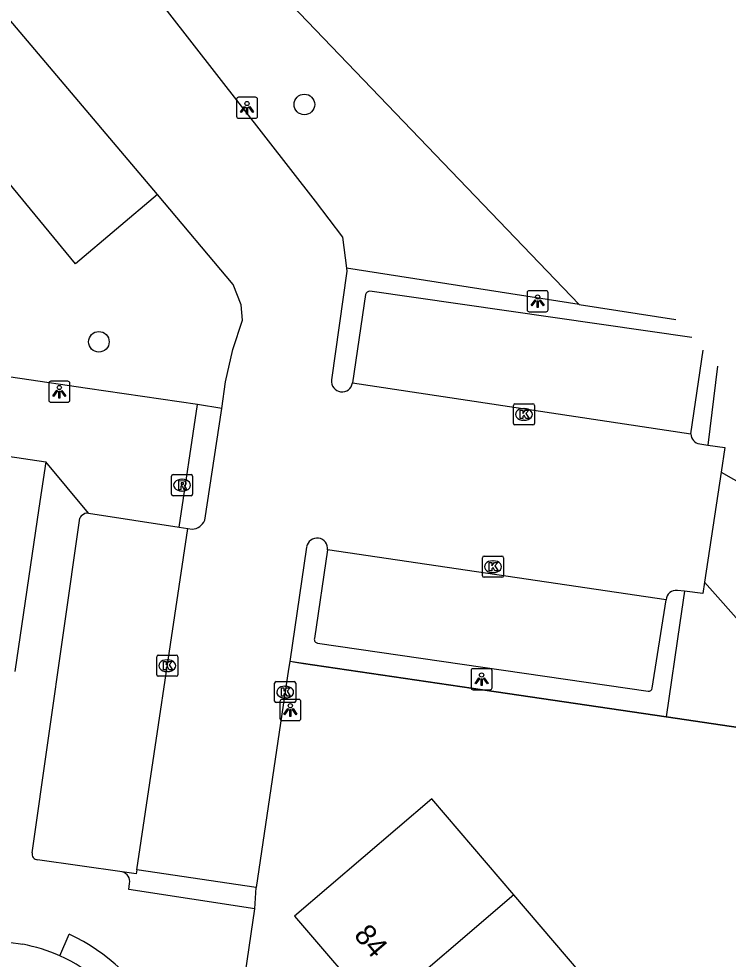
# Model space of a CAD drawing. Extents: x 164150 to 165261, y 382513 to 383432.
# Drawn here: x 164532.98 to 164566.64, y 383321.23 to 383365.81 of the extents above; entities that cross this region are included whole.
import ezdxf

# ---------------------------------------------------------------- set-up
doc = ezdxf.new("R2010")
doc.units = 0
for name, color, linetype in [('IMGEO_Boom', 7, 'Continuous'), ('IMGEO_Groenvoorziening', 7, 'Continuous'), ('IMGEO_Hek', 7, 'Continuous'), ('IMGEO_Kolk', 7, 'Continuous'), ('IMGEO_Lichtpunt', 7, 'Continuous'), ('IMGEO_Pand', 7, 'Continuous'), ('IMGEO_Pand_nummerreeks', 7, 'Continuous'), ('IMGEO_Parkeervlak_open', 7, 'Continuous'), ('IMGEO_Rijbaan_lokaal_open', 7, 'Continuous'), ('IMGEO_Rioolput', 7, 'Continuous'), ('IMGEO_Voetpad_open', 7, 'Continuous')]:
    doc.layers.add(name, color=color, linetype=linetype)

msp = doc.modelspace()

# ---------------------------------------------------------------- linework, layer by layer
at = {"layer": 'IMGEO_Boom'}
for centre in [(164546.528, 383361.744), (164536.778, 383350.494)]:
    msp.add_circle(centre, 0.489, dxfattribs=at)
at = {"layer": 'IMGEO_Groenvoorziening'}
for points in [[(164545.922, 383366.476), (164559.572, 383352.268)], [(164559.572, 383352.268), (164548.525, 383353.977)], [(164559.572, 383352.268), (164564.155, 383351.559)], [(164566.122, 383349.332), (164565.67, 383345.599)], [(164566.305, 383344.311), (164569.232, 383342.658), (164579.791, 383329.652), (164603.14, 383303.958), (164617.977, 383286.766), (164648.404, 383251.254), (164673.485, 383220.184), (164709.708, 383176.739), (164710.441, 383175.86), (164752.593, 383124.39), (164776.716, 383094.655), (164796.852, 383070.221), (164805.188, 383059.841), (164822.836, 383038.617), (164858.114, 382995.014), (164877.754, 382971.302), (164899.005, 382944.896), (164903.538, 382938.379)], [(164565.515, 383339.104), (164586.345, 383315.663), (164606.03, 383291.593), (164619.657, 383274.842), (164653.254, 383235.189), (164669.707, 383215.37), (164689.184, 383191.909), (164697.544, 383182.287), (164699.35, 383180.017), (164699.148, 383178.489), (164689.54, 383169.792), (164688.541, 383168.421), (164688.591, 383167.263)], [(164564.564, 383338.667), (164564.346, 383337.178), (164563.693, 383332.71)], [(164563.693, 383332.71), (164545.833, 383335.341)], [(164643.541, 383216.874), (164670.853, 383212.753), (164601.938, 383293.634), (164580.845, 383318.389), (164573.491, 383327.02), (164568.932, 383331.938), (164563.693, 383332.71)]]:
    msp.add_lwpolyline(points, dxfattribs=at)
at = {"layer": 'IMGEO_Hek'}
msp.add_lwpolyline([(164546.01, 383335.315), (164546.486, 383335.245), (164563.693, 383332.71), (164568.932, 383331.938), (164573.491, 383327.02), (164580.845, 383318.389), (164601.938, 383293.634), (164670.853, 383212.753), (164643.541, 383216.874), (164643.122, 383217.367), (164640.381, 383220.598), (164640.269, 383220.73)], dxfattribs=at)
at = {"layer": 'IMGEO_Kolk'}
for p, q in [((164556.521, 383347.552), (164557.373, 383347.552)), ((164556.446, 383346.626), (164556.446, 383347.478)), ((164556.934, 383347.332), (164556.959, 383347.332)), ((164557.447, 383347.478), (164557.447, 383346.626)), ((164556.957, 383346.772), (164556.932, 383346.772)), ((164557.373, 383346.552), (164556.521, 383346.552)), ((164554.977, 383339.404), (164554.977, 383340.256)), ((164555.052, 383340.33), (164555.904, 383340.33)), ((164555.465, 383340.11), (164555.49, 383340.11)), ((164555.978, 383340.256), (164555.978, 383339.404)), ((164555.488, 383339.55), (164555.463, 383339.55)), ((164555.904, 383339.33), (164555.052, 383339.33)), ((164539.523, 383334.711), (164539.523, 383335.563)), ((164539.598, 383335.637), (164540.45, 383335.637)), ((164540.524, 383335.563), (164540.524, 383334.711)), ((164540.011, 383335.417), (164540.036, 383335.417)), ((164540.45, 383334.637), (164539.598, 383334.637)), ((164540.034, 383334.857), (164540.009, 383334.857)), ((164545.116, 383333.462), (164545.116, 383334.314)), ((164545.191, 383334.388), (164546.043, 383334.388)), ((164545.604, 383334.168), (164545.629, 383334.168)), ((164546.117, 383334.314), (164546.117, 383333.462)), ((164546.043, 383333.388), (164545.191, 383333.388)), ((164545.627, 383333.608), (164545.602, 383333.608))]:
    msp.add_line(p, q, dxfattribs=at)
for points in [[(164556.521, 383347.552), (164557.373, 383347.552)], [(164556.446, 383346.626), (164556.446, 383347.478)], [(164556.767, 383347.252), (164556.89, 383347.252), (164556.89, 383347.101), (164557.02, 383347.252), (164557.184, 383347.252), (164557.038, 383347.101), (164557.191, 383346.852), (164557.039, 383346.852), (164556.954, 383347.016), (164556.89, 383346.949), (164556.89, 383346.852), (164556.767, 383346.852), (164556.767, 383347.252)], [(164557.447, 383347.478), (164557.447, 383346.626)], [(164557.373, 383346.552), (164556.521, 383346.552)], [(164554.977, 383339.404), (164554.977, 383340.256)], [(164555.052, 383340.33), (164555.904, 383340.33)], [(164555.298, 383340.03), (164555.421, 383340.03), (164555.421, 383339.879), (164555.551, 383340.03), (164555.715, 383340.03), (164555.569, 383339.879), (164555.722, 383339.63), (164555.57, 383339.63), (164555.485, 383339.794), (164555.421, 383339.727), (164555.421, 383339.63), (164555.298, 383339.63), (164555.298, 383340.03)], [(164555.978, 383340.256), (164555.978, 383339.404)], [(164555.904, 383339.33), (164555.052, 383339.33)], [(164539.523, 383334.711), (164539.523, 383335.563)], [(164539.598, 383335.637), (164540.45, 383335.637)], [(164540.524, 383335.563), (164540.524, 383334.711)], [(164539.844, 383335.337), (164539.967, 383335.337), (164539.967, 383335.186), (164540.097, 383335.337), (164540.261, 383335.337), (164540.115, 383335.186), (164540.268, 383334.937), (164540.116, 383334.937), (164540.031, 383335.101), (164539.967, 383335.034), (164539.967, 383334.937), (164539.844, 383334.937), (164539.844, 383335.337)], [(164540.45, 383334.637), (164539.598, 383334.637)], [(164545.116, 383333.462), (164545.116, 383334.314)], [(164545.191, 383334.388), (164546.043, 383334.388)], [(164546.117, 383334.314), (164546.117, 383333.462)], [(164545.437, 383334.088), (164545.56, 383334.088), (164545.56, 383333.937), (164545.69, 383334.088), (164545.854, 383334.088), (164545.708, 383333.937), (164545.861, 383333.688), (164545.709, 383333.688), (164545.624, 383333.852), (164545.56, 383333.785), (164545.56, 383333.688), (164545.437, 383333.688), (164545.437, 383334.088)], [(164546.043, 383333.388), (164545.191, 383333.388)]]:
    msp.add_lwpolyline(points, dxfattribs=at)
for centre, start, end in [((164556.523, 383347.476), 91.552, 178.448), ((164556.523, 383347.476), 91.552, 178.448), ((164557.371, 383347.476), 1.552, 88.448), ((164557.371, 383347.476), 1.552, 88.448), ((164556.523, 383346.628), 181.552, 268.448), ((164556.523, 383346.628), 181.552, 268.448), ((164557.371, 383346.628), 271.552, 358.448), ((164557.371, 383346.628), 271.552, 358.448), ((164555.054, 383340.254), 91.552, 178.448), ((164555.054, 383340.254), 91.552, 178.448), ((164555.902, 383340.254), 1.552, 88.448), ((164555.902, 383340.254), 1.552, 88.448), ((164555.054, 383339.406), 181.552, 268.448), ((164555.054, 383339.406), 181.552, 268.448), ((164555.902, 383339.406), 271.552, 358.448), ((164555.902, 383339.406), 271.552, 358.448), ((164539.6, 383335.561), 91.552, 178.448), ((164539.6, 383335.561), 91.552, 178.448), ((164540.448, 383335.561), 1.552, 88.448), ((164540.448, 383335.561), 1.552, 88.448), ((164539.6, 383334.713), 181.552, 268.448), ((164539.6, 383334.713), 181.552, 268.448), ((164540.448, 383334.713), 271.552, 358.448), ((164540.448, 383334.713), 271.552, 358.448), ((164545.193, 383334.312), 91.552, 178.448), ((164545.193, 383334.312), 91.552, 178.448), ((164546.041, 383334.312), 1.552, 88.448), ((164546.041, 383334.312), 1.552, 88.448), ((164545.193, 383333.464), 181.552, 268.448), ((164545.193, 383333.464), 181.552, 268.448), ((164546.041, 383333.464), 271.552, 358.448), ((164546.041, 383333.464), 271.552, 358.448)]:
    msp.add_arc(centre, 0.0765, start, end, dxfattribs=at)
for centre, major_axis, ratio, start_param, end_param in [((164556.933, 383347.052), (-0.387, 0.002), 0.722429, 4.712389, 7.853982), ((164556.958, 383347.052), (-0.39, 0.002), 0.717154, 1.570796, 4.712389), ((164555.464, 383339.83), (-0.387, 0.002), 0.722429, 4.712389, 7.853982), ((164555.489, 383339.83), (-0.39, 0.002), 0.717154, 1.570796, 4.712389), ((164540.01, 383335.137), (-0.387, 0.002), 0.722429, 4.712389, 7.853982), ((164540.035, 383335.137), (-0.39, 0.002), 0.717154, 1.570796, 4.712389), ((164545.603, 383333.888), (-0.387, 0.002), 0.722429, 4.712389, 7.853982), ((164545.628, 383333.888), (-0.39, 0.002), 0.717154, 1.570796, 4.712389)]:
    msp.add_ellipse(centre, major_axis=major_axis, ratio=ratio, start_param=start_param, end_param=end_param, dxfattribs=at)
at = {"layer": 'IMGEO_Lichtpunt'}
for p, q in [((164543.309, 383361.99), (164543.309, 383361.183)), ((164543.309, 383361.99), (164543.309, 383361.183)), ((164544.211, 383362.085), (164543.403, 383362.085)), ((164544.211, 383362.085), (164543.403, 383362.085)), ((164544.305, 383361.183), (164544.305, 383361.99)), ((164544.305, 383361.183), (164544.305, 383361.99)), ((164543.403, 383361.089), (164544.211, 383361.089)), ((164543.403, 383361.089), (164544.211, 383361.089)), ((164558, 383352.917), (164557.192, 383352.917)), ((164558, 383352.917), (164557.192, 383352.917)), ((164557.098, 383352.822), (164557.098, 383352.015)), ((164557.098, 383352.822), (164557.098, 383352.015)), ((164558.094, 383352.015), (164558.094, 383352.822)), ((164558.094, 383352.015), (164558.094, 383352.822)), ((164557.192, 383351.921), (164558, 383351.921)), ((164557.192, 383351.921), (164558, 383351.921)), ((164534.403, 383348.53), (164534.403, 383347.723)), ((164534.403, 383348.53), (164534.403, 383347.723)), ((164535.305, 383348.625), (164534.497, 383348.625)), ((164535.305, 383348.625), (164534.497, 383348.625)), ((164535.399, 383347.723), (164535.399, 383348.53)), ((164535.399, 383347.723), (164535.399, 383348.53)), ((164534.497, 383347.629), (164535.305, 383347.629)), ((164534.497, 383347.629), (164535.305, 383347.629)), ((164554.437, 383334.901), (164554.437, 383334.094)), ((164554.437, 383334.901), (164554.437, 383334.094)), ((164555.339, 383334.996), (164554.531, 383334.996)), ((164555.339, 383334.996), (164554.531, 383334.996)), ((164555.433, 383334.094), (164555.433, 383334.901)), ((164555.433, 383334.094), (164555.433, 383334.901)), ((164554.531, 383334), (164555.339, 383334)), ((164554.531, 383334), (164555.339, 383334)), ((164545.366, 383333.442), (164545.366, 383332.635)), ((164545.366, 383333.442), (164545.366, 383332.635)), ((164546.268, 383333.537), (164545.46, 383333.537)), ((164546.268, 383333.537), (164545.46, 383333.537)), ((164546.362, 383332.635), (164546.362, 383333.442)), ((164546.362, 383332.635), (164546.362, 383333.442)), ((164545.46, 383332.541), (164546.268, 383332.541)), ((164545.46, 383332.541), (164546.268, 383332.541))]:
    msp.add_line(p, q, dxfattribs=at)
for points in [[(164543.683, 383361.654), (164543.722, 383361.626), (164543.534, 383361.364), (164543.496, 383361.391), (164543.683, 383361.654)], [(164543.785, 383361.606), (164543.832, 383361.606), (164543.832, 383361.284), (164543.785, 383361.284), (164543.785, 383361.606)], [(164543.895, 383361.626), (164543.933, 383361.653), (164544.12, 383361.391), (164544.081, 383361.363), (164543.895, 383361.626)], [(164557.472, 383352.486), (164557.511, 383352.458), (164557.323, 383352.196), (164557.285, 383352.223), (164557.472, 383352.486)], [(164557.574, 383352.438), (164557.621, 383352.438), (164557.621, 383352.116), (164557.574, 383352.116), (164557.574, 383352.438)], [(164557.684, 383352.458), (164557.722, 383352.485), (164557.909, 383352.223), (164557.87, 383352.195), (164557.684, 383352.458)], [(164534.777, 383348.194), (164534.816, 383348.166), (164534.628, 383347.904), (164534.59, 383347.931), (164534.777, 383348.194)], [(164534.879, 383348.146), (164534.926, 383348.146), (164534.926, 383347.824), (164534.879, 383347.824), (164534.879, 383348.146)], [(164534.989, 383348.166), (164535.027, 383348.193), (164535.214, 383347.931), (164535.175, 383347.903), (164534.989, 383348.166)], [(164554.811, 383334.565), (164554.85, 383334.537), (164554.662, 383334.275), (164554.624, 383334.302), (164554.811, 383334.565)], [(164554.913, 383334.517), (164554.96, 383334.517), (164554.96, 383334.195), (164554.913, 383334.195), (164554.913, 383334.517)], [(164555.023, 383334.537), (164555.061, 383334.564), (164555.248, 383334.302), (164555.209, 383334.274), (164555.023, 383334.537)], [(164545.74, 383333.106), (164545.779, 383333.078), (164545.591, 383332.816), (164545.553, 383332.843), (164545.74, 383333.106)], [(164545.842, 383333.058), (164545.889, 383333.058), (164545.889, 383332.736), (164545.842, 383332.736), (164545.842, 383333.058)], [(164545.952, 383333.078), (164545.99, 383333.105), (164546.177, 383332.843), (164546.138, 383332.815), (164545.952, 383333.078)]]:
    msp.add_lwpolyline(points, dxfattribs=at)
for centre in [(164543.808, 383361.788), (164557.597, 383352.62), (164534.902, 383348.328), (164554.936, 383334.699), (164545.865, 383333.24)]:
    msp.add_circle(centre, 0.0994, dxfattribs=at)
for centre, start, end in [((164543.403, 383361.99), 90, 180), ((164543.403, 383361.99), 90, 180), ((164544.211, 383361.99), 0, 90), ((164544.211, 383361.99), 0, 90), ((164543.403, 383361.183), 180, 270), ((164543.403, 383361.183), 180, 270), ((164544.211, 383361.183), 270, 0), ((164544.211, 383361.183), 270, 360), ((164557.192, 383352.822), 90, 180), ((164557.192, 383352.822), 90, 180), ((164558, 383352.822), 0, 90), ((164558, 383352.822), 0, 90), ((164557.192, 383352.015), 180, 270), ((164557.192, 383352.015), 180, 270), ((164558, 383352.015), 270, 0), ((164558, 383352.015), 270, 360), ((164534.497, 383348.53), 90, 180), ((164534.497, 383348.53), 90, 180), ((164535.305, 383348.53), 0, 90), ((164535.305, 383348.53), 0, 90), ((164534.497, 383347.723), 180, 270), ((164534.497, 383347.723), 180, 270), ((164535.305, 383347.723), 270, 0), ((164535.305, 383347.723), 270, 360), ((164554.531, 383334.901), 90, 180), ((164554.531, 383334.901), 90, 180), ((164555.339, 383334.901), 0, 90), ((164555.339, 383334.901), 0, 90), ((164554.531, 383334.094), 180, 270), ((164554.531, 383334.094), 180, 270), ((164555.339, 383334.094), 270, 0), ((164555.339, 383334.094), 270, 360), ((164545.46, 383333.442), 90, 180), ((164545.46, 383333.442), 90, 180), ((164546.268, 383333.442), 0, 90), ((164546.268, 383333.442), 0, 90), ((164545.46, 383332.635), 180, 270), ((164545.46, 383332.635), 180, 270), ((164546.268, 383332.635), 270, 0), ((164546.268, 383332.635), 270, 360)]:
    msp.add_arc(centre, 0.0946, start, end, dxfattribs=at)
at = {"layer": 'IMGEO_Pand'}
for points in [[(164528.836, 383345.612), (164534.257, 383344.81)], [(164534.257, 383344.81), (164533.932, 383342.614), (164532.785, 383334.868)], [(164556.467, 383324.278), (164552.575, 383328.82), (164546.067, 383323.258), (164549.971, 383318.713)], [(164556.467, 383324.278), (164549.971, 383318.713)], [(164549.971, 383318.713), (164553.862, 383314.182), (164560.358, 383319.735), (164560.269, 383319.839), (164556.467, 383324.278)]]:
    msp.add_lwpolyline(points, dxfattribs=at)
at = {"layer": 'IMGEO_Parkeervlak_open'}
for points in [[(164539.555, 383357.479), (164535.662, 383354.185), (164519.834, 383373.4), (164523.47, 383376.478)], [(164564.912, 383350.702), (164549.64, 383352.897)], [(164549.43, 383352.732), (164548.81, 383348.547)], [(164564.869, 383346.125), (164565.444, 383350.099)], [(164547.627, 383340.624), (164547.003, 383336.429)], [(164563.034, 383334.076), (164563.687, 383338.267)], [(164547.15, 383336.206), (164562.838, 383333.927)]]:
    msp.add_lwpolyline(points, dxfattribs=at)
for centre, radius, start, end in [((164549.657, 383352.66), 0.238, 94.0167, 162.2977), ((164547.186, 383336.39), 0.188, 168.0034, 258.7818), ((164562.854, 383334.109), 0.183, 264.9925, 349.492)]:
    msp.add_arc(centre, radius, start, end, dxfattribs=at)
at = {"layer": 'IMGEO_Rijbaan_lokaal_open'}
for points in [[(164525.871, 383378.486), (164528.325, 383380.45), (164537.676, 383369.193), (164547.036, 383357.164), (164548.332, 383355.447), (164548.525, 383353.977)], [(164539.555, 383357.479), (164523.47, 383376.478)], [(164542.619, 383347.337), (164542.782, 383348.604), (164543.134, 383350.126), (164543.586, 383351.519), (164543.527, 383352.251), (164543.153, 383353.214), (164539.555, 383357.479)], [(164548.525, 383353.977), (164548.543, 383353.836), (164547.822, 383348.684)], [(164548.81, 383348.547), (164564.869, 383346.125)], [(164541.8, 383342.033), (164542.619, 383347.337)], [(164565.287, 383345.652), (164565.67, 383345.599)], [(164565.67, 383345.599), (164566.484, 383345.487), (164566.305, 383344.311)], [(164566.305, 383344.311), (164565.515, 383339.104)], [(164538.584, 383325.46), (164540.992, 383341.643)], [(164540.992, 383341.643), (164541.205, 383341.609)], [(164546.635, 383340.766), (164545.833, 383335.341)], [(164563.687, 383338.267), (164547.627, 383340.624)], [(164565.515, 383339.104), (164565.432, 383338.555), (164564.564, 383338.667)], [(164564.564, 383338.667), (164564.226, 383338.71)], [(164545.833, 383335.341), (164545.779, 383334.975), (164544.24, 383324.617)], [(164544.24, 383324.617), (164538.584, 383325.46)], [(164532.485, 383322.038), (164533.171, 383321.933)]]:
    msp.add_lwpolyline(points, dxfattribs=at)
for centre, radius, start, end in [((164548.317, 383348.619), 0.499, 172.5435, 351.6675), ((164565.343, 383346.123), 0.474, 179.7522, 263.1832), ((164541.156, 383342.307), 0.7, 274, 336.9477), ((164547.13, 383340.691), 0.501, 352.3599, 171.3475), ((164564.173, 383338.225), 0.488, 83.7728, 175.0603), ((164531.67, 383314.08), 7.995, 66.0019, 79.182), ((164531.66, 383314.056), 8.021, 0.9196, 66.0038)]:
    msp.add_arc(centre, radius, start, end, dxfattribs=at)
at = {"layer": 'IMGEO_Rioolput'}
for p, q in [((164540.224, 383343.271), (164540.224, 383344.123)), ((164540.299, 383344.197), (164541.151, 383344.197)), ((164540.712, 383343.977), (164540.737, 383343.977)), ((164541.225, 383344.123), (164541.225, 383343.271)), ((164541.151, 383343.197), (164540.299, 383343.197)), ((164540.735, 383343.417), (164540.71, 383343.417))]:
    msp.add_line(p, q, dxfattribs=at)
for points in [[(164540.224, 383343.271), (164540.224, 383344.123)], [(164540.299, 383344.197), (164541.151, 383344.197)], [(164541.225, 383344.123), (164541.225, 383343.271)], [(164540.813, 383343.895), (164540.561, 383343.897), (164540.561, 383343.497)], [(164540.561, 383343.497), (164540.685, 383343.497), (164540.685, 383343.659), (164540.696, 383343.659)], [(164540.739, 383343.816), (164540.685, 383343.816), (164540.685, 383343.735)], [(164540.685, 383343.735), (164540.737, 383343.735)], [(164540.743, 383343.63), (164540.814, 383343.497), (164540.954, 383343.497), (164540.889, 383343.623)], [(164541.151, 383343.197), (164540.299, 383343.197)]]:
    msp.add_lwpolyline(points, dxfattribs=at)
for centre, radius, start, end in [((164540.301, 383344.121), 0.0765, 91.552, 178.448), ((164540.301, 383344.121), 0.0765, 91.552, 178.448), ((164541.149, 383344.121), 0.0765, 1.552, 88.448), ((164541.149, 383344.121), 0.0765, 1.552, 88.448), ((164540.695, 383343.606), 0.0533, 26.0293, 88.6989), ((164540.721, 383343.924), 0.19, 274.7715, 282.9687), ((164540.745, 383343.72), 0.0964, 77.0061, 93.1865), ((164540.759, 383343.777), 0.0378, 276.6634, 79.6772), ((164540.812, 383343.785), 0.109, 350.3612, 89.416), ((164540.81, 383343.785), 0.112, 277.5842, 350.9817), ((164540.794, 383343.57), 0.108, 29.5134, 73.7905), ((164540.301, 383343.273), 0.0765, 181.552, 268.448), ((164540.301, 383343.273), 0.0765, 181.552, 268.448), ((164541.149, 383343.273), 0.0765, 271.552, 358.448), ((164541.149, 383343.273), 0.0765, 271.552, 358.448)]:
    msp.add_arc(centre, radius, start, end, dxfattribs=at)
for centre, major_axis, ratio, start_param, end_param in [((164540.711, 383343.697), (-0.387, 0.002), 0.722429, 4.712389, 7.853982), ((164540.736, 383343.697), (-0.39, 0.002), 0.717154, 1.570796, 4.712389)]:
    msp.add_ellipse(centre, major_axis=major_axis, ratio=ratio, start_param=start_param, end_param=end_param, dxfattribs=at)
at = {"layer": 'IMGEO_Voetpad_open'}
for points in [[(164541.451, 383347.518), (164536.236, 383348.287), (164526.587, 383349.71)], [(164540.588, 383341.709), (164541.451, 383347.518)], [(164542.619, 383347.337), (164541.451, 383347.518)], [(164536.279, 383342.366), (164534.257, 383344.81)], [(164536.279, 383342.366), (164540.588, 383341.709)], [(164533.611, 383326.271), (164535.867, 383342.127)], [(164540.588, 383341.709), (164540.992, 383341.643)], [(164537.883, 383325.363), (164533.873, 383325.938)], [(164538.584, 383325.46), (164538.555, 383325.269), (164537.883, 383325.363)], [(164544.174, 383323.62), (164538.193, 383324.529), (164538.231, 383324.819)], [(164544.174, 383323.62), (164544.24, 383324.617)], [(164543.186, 383316.778), (164543.739, 383320.602), (164544.174, 383323.62)], [(164534.922, 383321.384), (164535.375, 383322.414)]]:
    msp.add_lwpolyline(points, dxfattribs=at)
for centre, radius, start, end in [((164536.238, 383341.954), 0.409, 130.1696, 155.05), ((164536.245, 383341.95), 0.417, 85.3738, 130.5921), ((164533.889, 383326.22), 0.282, 169.5602, 266.8302), ((164537.783, 383324.916), 0.458, 347.7893, 77.4253), ((164531.214, 383313.675), 9.679, 355.0887, 64.5415)]:
    msp.add_arc(centre, radius, start, end, dxfattribs=at)

# ---------------------------------------------------------------- texts
at = {"layer": 'IMGEO_Pand_nummerreeks'}
msp.add_text('84', height=1, rotation=310.4621, dxfattribs=at).set_placement((164548.836, 383322.341))

doc.saveas('drawing.dxf')
